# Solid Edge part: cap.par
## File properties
Author: CADCIM
Template: Normal.par
Last saved by: CADCIM
Revision: 15
Application: Solid Edge
Accuracy: 0.99
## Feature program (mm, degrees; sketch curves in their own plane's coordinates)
base feature "unnamed BaseFeature 1"
pattern "unnamed Pattern 1"
pattern "unnamed Pattern 2"
Other named dimensions: "Hole_3": Diameter = 6 mm; CounterBoreDiameter = 8 mm
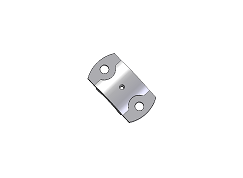
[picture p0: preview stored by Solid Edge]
